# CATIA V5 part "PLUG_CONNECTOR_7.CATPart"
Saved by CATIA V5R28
Part number: PLUG_CONNECTOR_7
Revision: ---
Publications: "MasterKeywayAxis", "InsertFrontFace", "InsertRearFace", "Logical Termination.1", "Logical Pin.1", "CCP", "Face_generated(CCP)", "Axis_generated(CCP)", "Face_generated(CCP).1", "BCP", "BCPRPoint_generated(BCP)", "BCPPlane_generated(BCP)", "BaCP", "Face_generated(BaCP)", "Face_generated(BaCP).1", "CaCP", "CaCPRPoint_generated(CaCP)", "Axis_generated(CaCP)", "Axis_generated(BaCP)", "Face"
Bounding box of the stored display mesh (mm): x 0 to 33.16, y -17.85 to 17.85, z -17.784 to 17.784
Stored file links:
  C:\Users\ajc8720\Documents\BOEING_WORK\0001-2CES\004-AP242\Boeing-Generic_Harness_R3\PLUG_CONNECTOR_7.CATPart
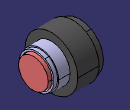
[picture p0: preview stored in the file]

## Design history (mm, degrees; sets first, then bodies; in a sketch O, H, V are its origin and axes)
Parameters
  PartNumber = "PLUG_CONNECTOR_7"
AxisSystem1 "MasterKeywayAxis": origin (0, 0, 0), X (1, 0, 0), Y (0, 1, 0), Z (0, 0, 1)
Set1 "EGF"
  Set2 "CCP"
    Point1 "CCPRPoint": (15.01 {= deleted_ShoulderFront}, 0, 0)
  Set3 "BaCP"
    Point2 "BaCPRPoint": (31 {= deleted_ShellLength}, 0, 0)
  Set4 "BCP"
    Plane1 "BCPPlane": type Offset, RefPlane face of Pad6, Offset 0, reversed
    Point3 "BCPRPoint": type OnPlane, Support Plane1, H 0, V 0, Direction (0, 1, 0)
  Set5 "CaCP"
    Point4 "CaCPRPoint": (15.01 {= deleted_ShoulderFront}, 0, 0)
Body1 "CouplingRing" (main body)
  Sketch1 on yz-plane, origin (0, 0, 0), H (0, 1, 0), V (0, 0, 1)
    circle A1 centre (0, 0) radius 17.85
    radius A1 = 17.85
  Pad1 "CouplingRing": profile Sketch1, direction (1, 0, 0), length 20.84 {= deleted_CouplingRingFront + deleted_CouplingRingLength}, opposite side length -1.68 {= -( deleted_CouplingRingFront )}
  Sketch2 on zx-plane, origin (0, 0, 0), H (-1, 0, 0), V (0, 0, 1)
    line L1 (-6.38, 17.85) -> (-1.68, 17.85)
    line L2 (-1.68, 17.85) -> (-1.68, 16.1)
    line L3 (-1.68, 16.1) -> (-6.38, 16.1)
    line L4 (-6.38, 16.1) -> (-6.38, 17.85)
    distance H L3 = 16.1
    distance H L1 = 17.85
    distance V L2 = 1.68
    length L1 = 4.7
    horizontal: L1 H, L3 H
    vertical: L2 V, L4 V
  Groove1 "CouplingRingRelief": profile Sketch2, axis Sketch2.H, angle 360
  Sketch3 on face of Pad1, origin (1.68, 0, 0), H (0, -1, 0), V (0, 0, 1)
    point P1 (0, 0)
    reference intersected line E1 through (0, 0) direction (-1, 0) from xy-plane
    reference intersected line E2 through (0, 0) direction (0, -1) from zx-plane
    coincidence: P1 E1, P1 E2
  Hole1 "CouplingRingID": placed by Sketch3, at (1.68, 0, 0) direction (1, 0, 0), diameter 30.52 {= deleted_CouplingRingThreadDia}, depth 18.3 {= deleted_CouplingRingThreadLength}, counterbore diameter 30.89 {= deleted_CouplingRingFrontID}, counterbore depth 2.14 {= deleted_CouplingRingFrontIDLength}
  Sketch4 on face of Hole1, origin (19.98, 0, 0), H (0, 1, 0), V (0, 0, -1)
    point P1 (0, 0)
    reference intersected line E1 through (0, 0) direction (0, 1) from zx-plane
    reference intersected line E2 through (0, 0) direction (1, 0) from xy-plane
    coincidence: P1 E1, P1 E2
  Hole2 "CouplingRingThruHole": placed by Sketch4, at (19.98, 0, 0) direction (1, 0, 0), diameter 25.4 {= deleted_CouplingRingThruDia}, through (limit type 6)
Body2 "Shell"
  Sketch5 on yz-plane, origin (0, 0, 0), H (0, 1, 0), V (0, 0, 1)
    circle A1 centre (0, 0) radius 11.75
    radius A1 = 11.75
  Pad2 "ShellFront": profile Sketch5, direction (1, 0, 0), length 15.01 {= deleted_ShoulderFront}
  Sketch6 on yz-plane, origin (0, 0, 0), H (0, 1, 0), V (0, 0, 1)
    circle A1 centre (0, 0) radius 12.5
    radius A1 = 12.5
  Pad3 "ShellBack": profile Sketch6, direction (1, 0, 0), length 31 {= deleted_ShellLength}, opposite side length -15.01 {= -( deleted_ShoulderFront )}
  Sketch7 on zx-plane, origin (0, 0, 0), H (-1, 0, 0), V (0, 0, 1)
    line L1 (-31, 12.5) -> (-23.89, 12.5)
    line L2 (-28.46, 12.5) -> (-28.46, 11.785)
    line L3 (-28.46, 11.785) -> (-31, 11.785)
    line L4 (-31, 11.785) -> (-31, 12.5)
    line L5 (-23.89, 12.5) -> (-23.89, 12.5)
    line L6 (-23.89, 12.5) -> (-28.46, 12.5)
    distance V L4 = 31
    length L1 = 7.11
    length L3 = 2.54
    distance H L3 = 11.785
    distance H L6 = 12.5
    distance L1 H = 12.5
    horizontal: L1 H, L3 H, L6 H
    vertical: L2 V, L4 V, L5 V
  Groove2 "AccyTeethThread": profile Sketch7, axis Sketch7.H, angle 360
  Sketch8 on yz-plane, origin (0, 0, 0), H (0, 1, 0), V (0, 0, 1)
    point P1 (-1.27, 0)
    line L1 (-1.27, 0) -> (1.27, 0)
    line L2 (1.27, 0) -> (1.27, 12.76)
    line L3 (1.27, 12.76) -> (-1.27, 12.76)
    line L4 (-1.27, 12.76) -> (-1.27, 0)
    length L3 = 2.54
    distance H L3 = 12.76
    coincidence: P1 H
    horizontal: L1 H, L3 H
    vertical: L2 V, L4 V
    symmetry: L2 L4 V
  Pad4 "MasterKeyway": profile Sketch8, direction (1, 0, 0), length 15.01 {= deleted_ShoulderFront}, opposite side length -0.76 {= - ( deleted_MasterKeyFront )}
  Sketch9 on face of Pad2, origin (0, 0, 0), H (0, -1, 0), V (0, 0, 1)
    point P1 (0, 0)
    reference intersected line E1 through (0, 0) direction (0, -1) from zx-plane
    reference intersected line E2 through (0, 0) direction (-1, 0) from xy-plane
    coincidence: P1 E1, P1 E2
  Hole3 "FrontShellID": placed by Sketch9, at (0, 0, 0) direction (1, 0, 0), diameter 20.16 {= deleted_ShellFrontID}, depth 20.46 {= deleted_ShellLength - deleted_ShellRearIDLength}
  Sketch10 on face of Pad3, origin (31, 0, 0), H (0, 1, 0), V (0, 0, 1)
    point P1 (0, 0)
    reference intersected line E1 through (0, 0) direction (0, 1) from zx-plane
    reference intersected line E2 through (0, 0) direction (-1, 0) from xy-plane
    coincidence: P1 E1, P1 E2
  Hole4 "RearShellID": placed by Sketch10, at (31, 0, 0) direction (-1, 0, 0), diameter 21.31 {= deleted_ShellRearID}, depth 10.54 {= deleted_ShellRearIDLength}
Body3 "Insert"
  Sketch11 on yz-plane, origin (0, 0, 0), H (0, 1, 0), V (0, 0, 1)
    circle A1 centre (0, 0) radius 9.87
    radius A1 = 9.87
  Pad5 "InsertOD": profile Sketch11, direction (1, 0, 0), length 20.46 {= deleted_InsertFront + deleted_InsertLength - deleted_GrommetLength}, opposite side length -0.1 {= -( deleted_InsertFront )}
  Sketch12 on yz-plane, origin (0, 0, 0), H (0, 1, 0), V (0, 0, 1)
    circle A1 centre (0, 0) radius 10.045
    radius A1 = 10.045
  Pad6 "GrommetOD": profile Sketch12, direction (1, 0, 0), length 33.16 {= deleted_InsertFront + deleted_InsertLength}, opposite side length -20.46 {= -( deleted_InsertFront + deleted_InsertLength - deleted_GrommetLength )}
Body4 "CCP"
  Sketch13 on face of Pad3, origin (15.01, 0, 0), H (0, 1, 0), V (0, 0, 1)
    arc A1 centre (0, 0) radius 1.016 from (-0.672, 0.762) to (0.672, 0.762) ccw
    line L1 (-0.672, 0.762) -> (0.672, 0.762)
    distance L1 H = 0.762
    radius A1 = 1.016
  Pad7: profile Sketch13, direction (1, 0, 0), length 0.508
Body5 "BaCP"
  Sketch14 on face of Pad3, origin (31, 0, 0), H (0, 1, 0), V (0, 0, 1)
    arc A1 centre (0, 0) radius 1.016 from (-0.672, 0.762) to (0.672, 0.762) ccw
    line L1 (-0.672, 0.762) -> (0.672, 0.762)
    distance L1 H = 0.762
    radius A1 = 1.016
  Sketch15 on face of Pad3, origin (31, 0, 0), H (0, 1, 0), V (0, 0, 1)
    circle A1 centre (0, 0) radius 1.27
    radius A1 = 1.27
  Pad8: profile Sketch15, direction (1, 0, 0), length 0.254, opposite side length 0.254
  Pocket1: profile Sketch14, direction (1, 0, 0), through (limit type 6)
